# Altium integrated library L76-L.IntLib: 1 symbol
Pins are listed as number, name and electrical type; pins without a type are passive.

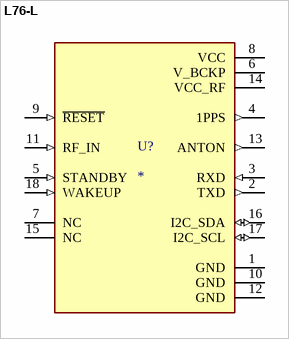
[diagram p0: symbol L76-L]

## L76-L
designator U?
GNSS module; 10.1mm 9.7mm 2.5mm; 0.6g, GPS, GLONASS, Galileo and QZSS; 33 tracking channels, 99 acquisition channels, and 210 PRN channels; Operating temperature of -40C to +85C.; MF: Quectel; MP: L76-L
footprint XCVR_L76-L
pins: 1 GND (power), 2 TXD (out), 3 RXD (in), 4 1PPS (out), 5 STANDBY (in), 6 V_BCKP (power), 7 NC, 8 VCC (power), 9 ~{RESET} (in), 10 GND (power), 11 RF_IN (in), 12 GND (power), 13 ANTON (out), 14 VCC_RF (power), 15 NC, 16 I2C_SDA (io), 17 I2C_SCL (io), 18 WAKEUP (in)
